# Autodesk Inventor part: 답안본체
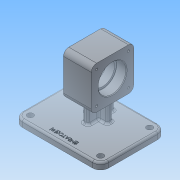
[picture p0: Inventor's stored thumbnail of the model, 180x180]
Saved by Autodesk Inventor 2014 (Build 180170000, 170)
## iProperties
Created: 2020-11
Part Number: 답안본체
Material: 알루미늄 6061
Document SubType Name: Modeling
Designer: NET
Density: 2.71 g/cm^3
Appearance: 알루미늄 - 평지
Mass: 685.745 g
Surface Area: 542.794 cm^2
Volume: 253.042 cm^3
Author: NET
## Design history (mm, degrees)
sketch "스케치1"
  geometry: L1 (-32, -32)-(32, -32); L2 (32, -32)-(32, 32); L3 (32, 32)-(-32, 32); L4 (-32, 32)-(-32, -32); L5 (-32, -32)-(32, 32); L6 (32, -32)-(-32, 32); 1 further point
  constraints: 12 end point, 2 midpoint, 2 parallel, 1 horizontal, 1 perpendicular
  dimensions: "d0" = 64 distance of L2.end L3.end; "d1" = 64 distance of L1.end L2.end
extrude "돌출1" new body sketch "스케치1" distance "d2" = 21; taper "d4" = 0 deg; dims "d3" = 21, "d5" = 0
sketch "스케치2"
  geometry: C1 r 18 at (0, 0); 1 further point
  constraints: 1 centre point, 1 coincident
  dimensions: "d6" = 36 diameter of C1
extrude "돌출2" cut sketch "스케치2" stored distance "d7" = 21; taper "d8" = 0 deg
sketch "스케치4"
  geometry: C1 r 18 at (0, 0) reference; C2 r 21 at (0, 0)
  constraints: 1 centre point, 1 coincident
  dimensions: "d9" = 42 diameter of C2
extrude "돌출3" cut sketch "스케치4" distance "d10" = 15; taper "d11" = 0 deg
sketch "스케치5"
  geometry: C1 r 18 at (0, 0) reference; C2 r 21 at (0, 0)
  constraints: 1 centre point, 1 coincident
  dimensions: "d12" = 42 diameter of C2
extrude "돌출4" cut sketch "스케치5" distance "d13" = 15; taper "d14" = 0 deg
node "작업 평면1"
sketch "스케치6"
  geometry: L1 (-44, 68)-(86, 68); L2 (86, 68)-(86, -30); L3 (86, -30)-(-44, -30); L4 (-44, -30)-(-44, 68); L5 (42, 64)-(42, 0) reference; 1 further point
  constraints: 8 end point, 2 parallel, 1 horizontal, 1 perpendicular
  dimensions: "d17" = 130 distance of L1.start L1.end; "d18" = 98 distance of L1.end L2.end; "d49" = 65 distance from line of L2 point (21, 32); "d50" = 62 distance from line of L3 point (21, 32)
extrude "돌출5" join sketch "스케치6" distance "d20" = 10; taper "d21" = 0 deg
fillet "모깎기1" dims "d22" = 8
sketch "스케치7"
  geometry: L1 (38, 28)-(4, 28); L2 (4, 28)-(4, 36); L3 (4, 36)-(38, 36); L4 (38, 36)-(38, 28); L5 (38, 28)-(4, 36); L6 (4, 28)-(38, 36); L7 (17, 12)-(25, 12); L8 (25, 12)-(25, 52); L9 (25, 52)-(17, 52); L10 (17, 52)-(17, 12); L11 (17, 12)-(25, 52); L12 (25, 12)-(17, 52); 1 further point
  constraints: 24 end point, 4 midpoint, 4 parallel, 2 horizontal, 2 perpendicular
  dimensions: "d23" = 8 distance of L8.end L9.end; "d24" = 8 distance of L1.end L2.end; "d25" = 40 distance between parallel lines of L9 L7; "d26" = 34 distance between parallel lines of L4 L2
extrude "돌출6" join sketch "스케치7" stored distance "d27" = 10; taper "d28" = 0 deg
fillet "모깎기2" dims "d29" = 12
sketch "스케치8"
  geometry: A1 r 12 centre (-32, -18) between (-44, -18) and (-32, -30) reference; A2 r 12 centre (74, -18) between (74, -30) and (86, -18) reference; A3 r 12 centre (74, 56) between (86, 56) and (74, 68) reference; A4 r 12 centre (-32, 56) between (-32, 68) and (-44, 56) reference; 5 further points
  constraints: 4 coincident
hole "구멍1" sketch "스케치8" at (-32, 56), (74, 56), (74, -18), (-32, -18) diameter "d30" = 9; stored, may be unused: countersink angle "d34" = 90 deg, drill point angle "d36" = 118 deg; dims "d31" = 6, "d32" = 4, "d33" = 2, "d35" = 8
fillet "모깎기3" dims "d37" = 3
fillet "모깎기4" dims "d38" = 0.3
chamfer "모따기1" distance "d39" = 1; stored, may be unused: second distance "d40" = 2, angle "d41" = 45 deg
fillet "모깎기5" dims "d42" = 3
fillet "모깎기6" dims "d43" = 3
fillet "모깎기7" dims "d44" = 3
sketch "스케치9"
  geometry: L1 (-44, 56)-(-44, -18) reference; L2 (-32, -30)-(74, -30) reference; 2 further points
  constraints: 1 other
  dimensions: "d45" = 65 distance from line of L1 point (21, -20); "d46" = 10 distance from line of L2 point (21, -20)
feature "엠보싱1" sketch "스케치9" dims "d0" = 64, "d1" = 64, "d47" = 0.5, "d48" = 0
sketch "스케치10"
  geometry: A1 r 8 centre (24, 24) between (32, 24) and (24, 32) reference; A2 r 8 centre (-24, 24) between (-24, 32) and (-32, 24) reference; A3 r 8 centre (-24, -24) between (-32, -24) and (-24, -32) reference; A4 r 8 centre (24, -24) between (24, -32) and (32, -24) reference; 4 further points
  constraints: 4 coincident
hole "구멍2" sketch "스케치10" at (-24, -24), (-24, 24), (24, 24), (24, -24) diameter "d51" = 3.242; stored, may be unused: countersink angle "d55" = 90 deg, drill point angle "d57" = 118 deg; dims "d52" = 8, "d53" = 4, "d54" = 2, "d56" = 10
sketch "스케치11"
  geometry: A1 r 8 centre (-24, 24) between (-24, 32) and (-32, 24) reference; A2 r 8 centre (-24, -24) between (-32, -24) and (-24, -32) reference; A3 r 8 centre (24, -24) between (24, -32) and (32, -24) reference; A4 r 8 centre (24, 24) between (32, 24) and (24, 32) reference; 4 further points
  constraints: 4 coincident
hole "구멍3" sketch "스케치11" at (-24, 24), (24, 24), (24, -24), (-24, -24) diameter "d58" = 3.242; stored, may be unused: countersink angle "d62" = 90 deg, drill point angle "d64" = 118 deg; dims "d59" = 8, "d60" = 4, "d61" = 2, "d63" = 10
node "솔리드1"
other parameters: "d15" = -102
